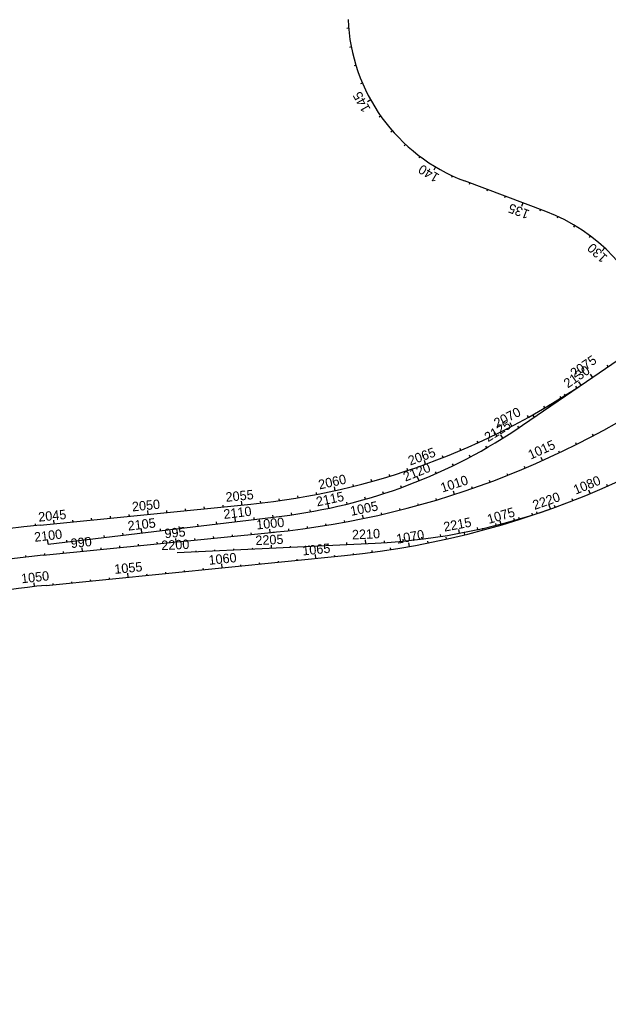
# Model space of a CAD drawing. Extents: x 448091 to 665917, y 1461380 to 1587607.
# Drawn here: x 464523 to 467646, y 1518185 to 1523323 of the extents above; entities that cross this region are included whole.
import ezdxf

# ---------------------------------------------------------------- set-up
doc = ezdxf.new("R2010")
doc.units = 0
doc.layers.add('TextShtNo', color=7, linetype='Continuous')
doc.layers.add('TextTitle', color=7, linetype='Continuous')

msp = doc.modelspace()

# ---------------------------------------------------------------- linework, layer by layer
at = {"layer": 'TextShtNo'}
for p, q in [((467313.6, 1522305), (466882.6, 1522467.4)), ((467528.9, 1521405.5), (468780, 1522262.6)), ((467190.5, 1521173.6), (467528.9, 1521405.5)), ((464632.4, 1520644), (465750.1, 1520755.8)), ((464676, 1520543.9), (465913.4, 1520692.7)), ((464648.3, 1520484.8), (465875.6, 1520607.6)), ((465360.1, 1520499.7), (466408.3, 1520549.4)), ((464664.2, 1520325.6), (466246.5, 1520483.9))]:
    msp.add_line(p, q, dxfattribs=at)
for centre, radius, start, end in [((467219.1, 1523361), 954.9, 182.31, 249.3631), ((466977.1, 1521411.4), 954.9, 17.4964, 69.3631), ((465790.4, 1525044.8), 4583.7, 275.7106, 313.4855), ((465419.5, 1525168.5), 4583.7, 275.5856, 307.7648), ((465370.1, 1524556.6), 3819.7, 275.7106, 304.4155), ((465571.4, 1523537), 2864.8, 276.8562, 304.4154), ((466253.5, 1523819.7), 3274, 272.711, 290.7066), ((465218.4, 1514783.7), 5889.6, 95.7106, 122.67461), ((465218.4, 1514783.7), 5729.6, 95.71059, 143.58272), ((465218.4, 1514783.6), 5569.7, 95.7106, 103.7772)]:
    msp.add_arc(centre, radius, start, end, dxfattribs=at)
at = {"layer": 'TextTitle'}
for p, q in [((466268.1, 1523275.3), (466258.1, 1523274.4)), ((466282.2, 1523176.4), (466272.4, 1523174.4)), ((466306.7, 1523079.4), (466297.1, 1523076.5)), ((466341.1, 1522985.6), (466331.9, 1522981.7)), ((466385.2, 1522895.9), (466367.7, 1522886.1)), ((466438.3, 1522811.3), (466430.2, 1522805.5)), ((466500.1, 1522732.7), (466492.6, 1522726.1)), ((466569.7, 1522660.9), (466562.9, 1522653.6)), ((466646.4, 1522596.9), (466640.4, 1522588.9)), ((466729.5, 1522541.2), (466719.2, 1522524)), ((466817.8, 1522494.5), (466813.6, 1522485.4)), ((466910.4, 1522456.9), (466906.9, 1522447.5)), ((467004, 1522421.6), (467000.5, 1522412.3)), ((467097.6, 1522386.4), (467094.1, 1522377)), ((467191.2, 1522351.1), (467184.1, 1522332.4)), ((467284.8, 1522315.9), (467281.3, 1522306.5)), ((467377.4, 1522278.3), (467373.2, 1522269.2)), ((467465.8, 1522231.7), (467460.7, 1522223.1)), ((467548.9, 1522176.1), (467542.9, 1522168.1)), ((467625.7, 1522112.2), (467612.1, 1522097.5)), ((467561.2, 1521427.6), (467549.9, 1521444.1)), ((467643.7, 1521484.1), (467638, 1521492.3)), ((467643.7, 1521484.1), (467641.3, 1521487.6)), ((467500.5, 1521386), (467489.2, 1521402.5)), ((467561.2, 1521427.6), (467558.8, 1521431.1)), ((467478.4, 1521371.5), (467472.9, 1521379.8)), ((467478.4, 1521371.5), (467476.1, 1521375)), ((467394.3, 1521317.4), (467389, 1521325.8)), ((467394.3, 1521317.4), (467392.1, 1521321)), ((467418, 1521329.5), (467412.3, 1521337.7)), ((467308.8, 1521265.5), (467303.8, 1521274.1)), ((467308.8, 1521265.5), (467306.7, 1521269.2)), ((467335.5, 1521272.9), (467329.8, 1521281.2)), ((467222, 1521215.8), (467217.2, 1521224.6)), ((467222, 1521215.8), (467219.9, 1521219.6)), ((467253, 1521216.4), (467247.3, 1521224.7)), ((467133.9, 1521168.5), (467124.7, 1521186.3)), ((467170.4, 1521160), (467164.9, 1521168.3)), ((466954.2, 1521080.8), (466950.1, 1521089.9)), ((466954.2, 1521080.8), (466952.4, 1521084.8)), ((467044.7, 1521123.5), (467040.3, 1521132.5)), ((467044.7, 1521123.5), (467042.8, 1521127.4)), ((467086.5, 1521105.6), (467075.9, 1521122.6)), ((467565.4, 1521118.2), (467561.4, 1521125.8)), ((466862.7, 1521040.6), (466858.8, 1521049.8)), ((466862.7, 1521040.6), (466861, 1521044.5)), ((467000.7, 1521054.2), (466995.7, 1521062.9)), ((467386.7, 1521028.4), (467383, 1521036.2)), ((467476.5, 1521072.3), (467472.7, 1521080)), ((466676.6, 1520967.3), (466669.8, 1520986.1)), ((466770.1, 1521002.7), (466766.5, 1521012)), ((466770.1, 1521002.7), (466768.6, 1521006.7)), ((466913.2, 1521005.9), (466908.5, 1521014.7)), ((467295.9, 1520986.5), (467288.3, 1521003.5)), ((466582.2, 1520934.3), (466579, 1520943.8)), ((466582.2, 1520934.3), (466580.9, 1520938.4)), ((466676.6, 1520967.3), (466675.2, 1520971.3)), ((466824.1, 1520960.6), (466819.7, 1520969.6)), ((467204.2, 1520946.6), (467200.9, 1520954.5)), ((466391, 1520875.8), (466388.3, 1520885.5)), ((466391, 1520875.8), (466389.8, 1520880)), ((466487, 1520903.8), (466484.1, 1520913.4)), ((466487, 1520903.8), (466485.7, 1520907.9)), ((466641.3, 1520879.5), (466633.8, 1520898)), ((466733.4, 1520918.4), (466729.3, 1520927.6)), ((467018.4, 1520872.7), (467015.4, 1520880.8)), ((467111.7, 1520908.6), (467108.5, 1520916.6)), ((466196.9, 1520827.4), (466192.5, 1520847.7)), ((466196.9, 1520827.4), (466196, 1520831.6)), ((466294.3, 1520850.4), (466291.9, 1520860.1)), ((466294.3, 1520850.4), (466293.2, 1520854.5)), ((466547.9, 1520843.7), (466544.5, 1520853.1)), ((466924.3, 1520838.9), (466921.5, 1520847)), ((467549, 1520811.9), (467541.3, 1520830.4)), ((467640.9, 1520851.3), (467636.9, 1520860.4)), ((467640.9, 1520851.3), (467639.2, 1520855.2)), ((465901.8, 1520774.1), (465900.4, 1520784)), ((465901.8, 1520774.1), (465901.2, 1520778.3)), ((466000.6, 1520789.3), (465999, 1520799.1)), ((466000.6, 1520789.3), (465999.9, 1520793.5)), ((466099, 1520807.1), (466097.1, 1520816.9)), ((466099, 1520807.1), (466098.2, 1520811.3)), ((466357.6, 1520782.2), (466354.9, 1520791.8)), ((466453.3, 1520811.3), (466450.2, 1520820.8)), ((466734, 1520777.3), (466731.5, 1520785.6)), ((466829.5, 1520807.1), (466823.8, 1520824.8)), ((467456.2, 1520774.5), (467452.6, 1520783.8)), ((467456.2, 1520774.5), (467454.7, 1520778.5)), ((467549, 1520811.9), (467547.3, 1520815.9)), ((465404.6, 1520721.3), (465403.6, 1520731.2)), ((465404.6, 1520721.3), (465404.2, 1520725.5)), ((465504.1, 1520731.2), (465503.1, 1520741.2)), ((465504.1, 1520731.2), (465503.7, 1520735.5)), ((465603.6, 1520741.2), (465602.7, 1520751.1)), ((465603.6, 1520741.2), (465603.2, 1520745.4)), ((465703.2, 1520751.1), (465701.2, 1520771)), ((465703.2, 1520751.1), (465702.7, 1520755.4)), ((465802.6, 1520761.4), (465801.5, 1520771.4)), ((465802.6, 1520761.4), (465802.1, 1520765.7)), ((466065.4, 1520715.1), (466063.7, 1520724.9)), ((466163.6, 1520734.1), (466159.4, 1520753.6)), ((466261, 1520756.4), (466258.6, 1520766.1)), ((466541.2, 1520724.2), (466539.1, 1520732.5)), ((466637.9, 1520749.7), (466635.6, 1520758)), ((467338.1, 1520730.6), (467331.5, 1520749.5)), ((467362.7, 1520739.2), (467359.3, 1520748.6)), ((467362.7, 1520739.2), (467361.2, 1520743.2)), ((464907.1, 1520671.5), (464906.1, 1520681.5)), ((464907.1, 1520671.5), (464906.7, 1520675.8)), ((465006.6, 1520681.5), (465005.6, 1520691.4)), ((465006.6, 1520681.5), (465006.2, 1520685.7)), ((465106.1, 1520691.4), (465105.1, 1520701.4)), ((465106.1, 1520691.4), (465105.7, 1520695.7)), ((465205.6, 1520701.4), (465203.6, 1520722)), ((465205.6, 1520701.4), (465205.2, 1520705.6)), ((465305.1, 1520711.3), (465304.1, 1520721.3)), ((465305.1, 1520711.3), (465304.7, 1520715.6)), ((465668.8, 1520663.3), (465666.4, 1520683.1)), ((465768.1, 1520675.2), (465766.9, 1520685.1)), ((465867.4, 1520687.1), (465866.2, 1520697.1)), ((465966.6, 1520699.6), (465965.2, 1520709.5)), ((466346.3, 1520679.5), (466342.5, 1520697.7)), ((466444, 1520700.8), (466442.1, 1520709.2)), ((467147.5, 1520670.1), (467144.8, 1520679.8)), ((467173.4, 1520674.7), (467170.4, 1520684.3)), ((467243.3, 1520698.9), (467240.3, 1520708.4)), ((467268.4, 1520705.9), (467265.2, 1520715.4)), ((464608.6, 1520641.6), (464607.6, 1520651.6)), ((464608.6, 1520641.6), (464608.2, 1520645.9)), ((464708.1, 1520651.6), (464706.1, 1520671.5)), ((464807.6, 1520661.6), (464806.6, 1520671.5)), ((464807.6, 1520661.6), (464807.2, 1520665.8)), ((465172.4, 1520603.6), (465170, 1520623.4)), ((465271.7, 1520615.5), (465270.5, 1520625.4)), ((465371, 1520627.4), (465369.8, 1520637.4)), ((465470.2, 1520639.4), (465469, 1520649.3)), ((465569.5, 1520651.3), (465568.3, 1520661.3)), ((465852.1, 1520605.2), (465850.2, 1520623.7)), ((465951.5, 1520615.8), (465950.5, 1520624.3)), ((466050.7, 1520628.5), (466049.5, 1520637)), ((466149.6, 1520643.3), (466148.2, 1520651.8)), ((466248.1, 1520660.3), (466246.6, 1520668.8)), ((466953.6, 1520621.4), (466951.4, 1520631.2)), ((466981.4, 1520618.6), (466978.8, 1520628.2)), ((467050.9, 1520644.3), (467048.5, 1520654)), ((467077.7, 1520645.6), (467072.1, 1520664.8)), ((464874.5, 1520567.8), (464873.3, 1520577.7)), ((464973.8, 1520579.7), (464972.6, 1520589.6)), ((465073.1, 1520591.6), (465071.9, 1520601.6)), ((465354.6, 1520555.5), (465352.7, 1520574)), ((465454.1, 1520565.4), (465453.2, 1520574)), ((465553.6, 1520575.4), (465552.7, 1520583.9)), ((465653.1, 1520585.3), (465652.2, 1520593.9)), ((465752.6, 1520595.3), (465751.7, 1520603.8)), ((466658, 1520570.8), (466656.8, 1520580.7)), ((466757, 1520584.7), (466755.5, 1520594.5)), ((466787.2, 1520570.8), (466785.1, 1520580.6)), ((466855.6, 1520601.5), (466851.9, 1520621.2)), ((466884.6, 1520593.6), (466882.2, 1520603.3)), ((464676, 1520543.9), (464673.6, 1520563.7)), ((464775.2, 1520555.8), (464774.1, 1520565.7)), ((464857.1, 1520505.7), (464855.2, 1520524.2)), ((464956.6, 1520515.7), (464955.7, 1520524.2)), ((465056.1, 1520525.6), (465055.2, 1520534.2)), ((465155.6, 1520535.6), (465154.7, 1520544.1)), ((465255.1, 1520545.5), (465254.2, 1520554.1)), ((465759.7, 1520518.7), (465759.5, 1520523)), ((465859.6, 1520523.4), (465858.9, 1520537.7)), ((465959.5, 1520528.1), (465959.3, 1520532.4)), ((466059.4, 1520532.8), (466059.2, 1520537.1)), ((466159.2, 1520537.6), (466159, 1520541.9)), ((466259.1, 1520542.3), (466258.7, 1520552.3)), ((466359, 1520547), (466358.1, 1520567)), ((466458.9, 1520552.2), (466458.3, 1520562.1)), ((466492.5, 1520515.2), (466491, 1520525.1)), ((466558.6, 1520560), (466557.6, 1520569.9)), ((466591.1, 1520531.6), (466587.7, 1520551.3)), ((466689.4, 1520550.1), (466687.4, 1520559.9)), ((464558.6, 1520475.1), (464557.6, 1520483.7)), ((464658, 1520485.8), (464657.2, 1520494.4)), ((464757.5, 1520495.8), (464756.7, 1520504.3)), ((465460, 1520504.5), (465459.8, 1520508.8)), ((465559.9, 1520509.2), (465559.7, 1520513.5)), ((465659.8, 1520513.9), (465659.6, 1520518.2)), ((466095.3, 1520468.7), (466093.2, 1520489.4)), ((466095.3, 1520468.7), (466094.8, 1520473)), ((466194.8, 1520478.7), (466194.2, 1520484.4)), ((466194.8, 1520478.7), (466194.3, 1520483)), ((466294.3, 1520488.9), (466293.6, 1520494.6)), ((466294.3, 1520488.9), (466293.8, 1520493.2)), ((466393.5, 1520501), (466392.2, 1520510.9)), ((465597.8, 1520419), (465595.7, 1520439.6)), ((465597.8, 1520419), (465597.3, 1520423.3)), ((465697.3, 1520428.9), (465696.7, 1520434.7)), ((465697.3, 1520428.9), (465696.8, 1520433.2)), ((465796.8, 1520438.9), (465796.2, 1520444.6)), ((465796.8, 1520438.9), (465796.3, 1520443.2)), ((465896.3, 1520448.8), (465895.7, 1520454.6)), ((465896.3, 1520448.8), (465895.8, 1520453.1)), ((465995.8, 1520458.8), (465995.2, 1520464.5)), ((465995.8, 1520458.8), (465995.3, 1520463.1)), ((465000.7, 1520359.3), (465000.2, 1520365)), ((465100.2, 1520369.2), (465098.2, 1520389.9)), ((465100.2, 1520369.2), (465099.8, 1520373.5)), ((465199.7, 1520379.2), (465199.2, 1520384.9)), ((465199.7, 1520379.2), (465199.3, 1520383.5)), ((465299.2, 1520389.1), (465298.7, 1520394.8)), ((465299.2, 1520389.1), (465298.8, 1520393.4)), ((465398.7, 1520399.1), (465398.2, 1520404.8)), ((465398.7, 1520399.1), (465398.3, 1520403.4)), ((465498.3, 1520409), (465497.7, 1520414.8)), ((465498.3, 1520409), (465497.8, 1520413.3)), ((464602.8, 1520319.1), (464600.5, 1520339)), ((464702.2, 1520329.4), (464701.6, 1520335.1)), ((464702.2, 1520329.4), (464701.8, 1520333.7)), ((464801.7, 1520339.4), (464801.2, 1520345.1)), ((464801.7, 1520339.4), (464801.3, 1520343.7)), ((464901.2, 1520349.3), (464900.7, 1520355)), ((464901.2, 1520349.3), (464900.8, 1520353.6)), ((465000.7, 1520359.3), (465000.3, 1520363.6))]:
    msp.add_line(p, q, dxfattribs=at)

# ---------------------------------------------------------------- texts
for s, rotation, p in [('145', 119.1492, (466385.9, 1522848.6)), ('140', 149.1492, (466753.4, 1522499.5)), ('135', 159.3631, (467231.3, 1522309.9)), ('130', 137.2136, (467644.3, 1522065.8)), ('2075', 34.4155, (467465.4, 1521422.6)), ('2130', 34.4154, (467429.9, 1521367.9)), ('2070', 27.5023, (467054.3, 1521158.6)), ('2125', 31.9294, (467007.8, 1521083.3)), ('1015', 24.1657, (467233.3, 1520991.1)), ('2065', 20.0023, (466594.5, 1520959.8)), ('2120', 21.9294, (466569.6, 1520874.7)), ('2060', 12.5023, (466114.1, 1520833.3)), ('1010', 17.9157, (466764.9, 1520816.7)), ('1080', 22.5608, (467472.3, 1520805.7)), ('2055', 5.7106, (465618.8, 1520767.7)), ('2050', 5.7106, (465122.5, 1520717)), ('2115', 11.9294, (466101.8, 1520743.3)), ('2220', 19.3472, (467253.9, 1520724.7)), ('2045', 5.7106, (464625.8, 1520662.6)), ('2110', 6.8562, (465608.2, 1520677.1)), ('1005', 11.6657, (466282.3, 1520693.3)), ('1075', 16.3108, (467011.3, 1520650.6)), ('2105', 6.8562, (465100.2, 1520615.1)), ('1000', 5.7106, (465781.2, 1520621.3)), ('2215', 10.5972, (466776.2, 1520610)), ('2100', 6.8562, (464604.4, 1520555.8)), ('995', 5.7106, (465294.7, 1520574.6)), ('2210', 2.711, (466287.2, 1520568.6)), ('990', 5.7106, (464797.7, 1520522.9)), ('2205', 2.711, (465775.1, 1520538.6)), ('1070', 10.0608, (466526, 1520545.7)), ('2200', 2.711, (465276.3, 1520512.1)), ('1065', 5.7106, (466025.3, 1520483.8)), ('1060', 5.7106, (465528.3, 1520434.1)), ('1055', 5.7106, (465028.9, 1520386)), ('1050', 6.3465, (464535, 1520336.2))]:
    msp.add_text(s, height=50, rotation=rotation, dxfattribs=at).set_placement(p)

doc.saveas('drawing.dxf')
